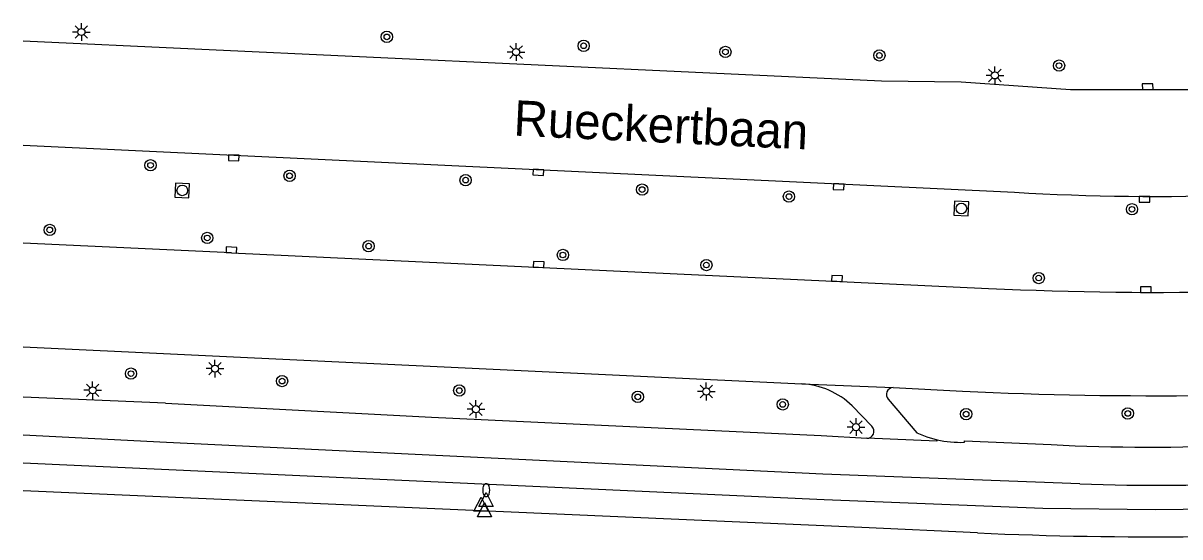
# Model space of a CAD drawing. Extents: x 132573 to 132944, y 398226 to 398676.
# Drawn here: x 132573 to 132654.8, y 398531 to 398567.3 of the extents above; entities that cross this region are included whole.
import ezdxf

# ---------------------------------------------------------------- set-up
doc = ezdxf.new("R2010")
doc.units = 0
for name, color, linetype in [('gg-anno-openbare ruimte label', 7, 'Continuous'), ('gg-knt-verharding', 7, 'Continuous'), ('gt-symb-boom', 7, 'Continuous'), ('gt-symb-brandkraan', 7, 'Continuous'), ('gt-symb-kolk', 7, 'Continuous'), ('gt-symb-lichtmast', 7, 'Continuous'), ('gt-symb-rioolschacht', 7, 'Continuous'), ('gt-symb-waterafsluiter', 7, 'Continuous')]:
    doc.layers.add(name, color=color, linetype=linetype)

msp = doc.modelspace()

# ---------------------------------------------------------------- linework, layer by layer
at = {"layer": 'gg-knt-verharding'}
for p, q in [((132573.021, 398558.665), (132587.916, 398557.963)), ((132587.916, 398557.963), (132643.07, 398555.33)), ((132587.734, 398551.055), (132573.021, 398551.736)), ((132587.734, 398551.055), (132641.243, 398548.55)), ((132573.021, 398544.411), (132628.051, 398541.809)), ((132628.051, 398541.809), (132634.494, 398541.539)), ((132583.077, 398540.449), (132573.021, 398540.872)), ((132634.494, 398541.539), (132639.4, 398541.29)), ((132632.997, 398538.808), (132631.596, 398540.256)), ((132639.54, 398537.68), (132639.553, 398537.781)), ((132639.553, 398537.781), (132645.663, 398537.514)), ((132629.629, 398533.623), (132573.021, 398536.217))]:
    msp.add_line(p, q, dxfattribs=at)
for points in [[(132573.021, 398566.028), (132633.671, 398563.201), (132639.312, 398563.126), (132647.044, 398562.601), (132652.489, 398562.588)], [(132583.077, 398540.449), (132601.878, 398539.466), (132629.419, 398538.153), (132632.633, 398537.963)], [(132634.149, 398540.722), (132636.163, 398538.34), (132636.87, 398538.066), (132637.6, 398537.863)], [(132647.686, 398534.74), (132629.537, 398535.429), (132583.159, 398537.66), (132573.021, 398538.184)], [(132637.6, 398537.863), (132637.582, 398537.756), (132632.633, 398537.963)], [(132640.467, 398531.279), (132632.29, 398531.665), (132573.021, 398534.264)], [(132678.938, 398533.726), (132660.959, 398533.003), (132653.017, 398532.913), (132645.08, 398533.003), (132629.629, 398533.623)]]:
    msp.add_lwpolyline(points, dxfattribs=at)
for centre, radius, start, end in [((132653.166, 398802.793), 240.206, 269.83859, 273.81384), ((132652.991, 398725.107), 170.066, 266.65564, 277.53525), ((132653.172, 398797.222), 248.958, 267.25349, 275.54025), ((132627.755, 398536.311), 5.506, 45.76621, 86.91909), ((132653.108, 398834.104), 293.135, 267.31972, 274.07391), ((132634.508, 398541.052), 0.487, 91.61115, 222.60246), ((132632.652, 398538.456), 0.493, 267.81374, 45.57648), ((132639.288, 398545.388), 7.712, 257.35342, 271.86906), ((132652.589, 398674.401), 137.062, 267.10354, 272.76093), ((132653.037, 398682.544), 147.9, 267.92677, 273.08843), ((132653.056, 398819.67), 288.666, 267.50056, 270.57669)]:
    msp.add_arc(centre, radius, start, end, dxfattribs=at)
at = {"layer": 'gt-symb-boom'}
for centre, radius in [((132598.723, 398566.307), 0.4), ((132598.723, 398566.307), 0.2), ((132612.631, 398565.676), 0.4), ((132612.631, 398565.676), 0.2), ((132622.65, 398565.24), 0.4), ((132622.65, 398565.24), 0.2), ((132633.527, 398564.995), 0.4), ((132633.527, 398564.995), 0.2), ((132646.222, 398564.276), 0.4), ((132646.222, 398564.276), 0.2), ((132582.022, 398557.238), 0.4), ((132582.022, 398557.238), 0.2), ((132591.848, 398556.496), 0.4), ((132591.848, 398556.496), 0.2), ((132604.292, 398556.19), 0.4), ((132604.292, 398556.19), 0.2), ((132616.764, 398555.525), 0.4), ((132616.764, 398555.525), 0.2), ((132627.138, 398555.03), 0.4), ((132627.138, 398555.03), 0.2), ((132651.379, 398554.13), 0.4), ((132651.379, 398554.13), 0.2), ((132574.9, 398552.676), 0.4), ((132574.9, 398552.676), 0.2), ((132586.032, 398552.109), 0.4), ((132586.032, 398552.109), 0.2), ((132597.435, 398551.53), 0.4), ((132597.435, 398551.53), 0.2), ((132611.163, 398550.905), 0.4), ((132611.163, 398550.905), 0.2), ((132621.302, 398550.196), 0.4), ((132621.302, 398550.196), 0.2), ((132644.787, 398549.28), 0.4), ((132644.787, 398549.28), 0.2), ((132580.643, 398542.528), 0.4), ((132580.643, 398542.528), 0.2), ((132591.321, 398542.003), 0.4), ((132591.321, 398542.003), 0.2), ((132603.842, 398541.335), 0.4), ((132603.842, 398541.335), 0.2), ((132616.457, 398540.888), 0.4), ((132616.457, 398540.888), 0.2), ((132626.695, 398540.354), 0.4), ((132626.695, 398540.354), 0.2), ((132639.658, 398539.67), 0.4), ((132651.082, 398539.717), 0.4), ((132639.658, 398539.67), 0.2), ((132651.082, 398539.717), 0.2)]:
    msp.add_circle(centre, radius, dxfattribs=at)
at = {"layer": 'gt-symb-brandkraan'}
for centre, radius, start, end in [((132606.436, 398534.302), 0.938, 163.10799, 196.89205), ((132608.409, 398533.703), 3, 162.43309, 163.10799), ((132605.745, 398534.546), 0.206, 17.56695, 162.43309), ((132603.081, 398533.703), 3, 16.89206, 17.56695), ((132605.054, 398534.302), 0.938, 343.10797, 16.89206), ((132608.409, 398534.901), 3, 196.89205, 197.56694), ((132605.745, 398534.058), 0.206, 197.56694, 342.43307), ((132603.081, 398534.901), 3, 342.43307, 343.10797)]:
    msp.add_arc(centre, radius, start, end, dxfattribs=at)
at = {"layer": 'gt-symb-kolk'}
for points in [[(132652.489, 398562.588), (132652.864, 398562.594), (132652.857, 398562.994), (132652.108, 398562.982), (132652.114, 398562.582), (132652.489, 398562.588)], [(132587.916, 398557.963), (132587.541, 398557.98), (132587.523, 398557.581), (132588.272, 398557.546), (132588.291, 398557.946), (132587.916, 398557.963)], [(132609.44, 398556.936), (132609.065, 398556.953), (132609.047, 398556.554), (132609.796, 398556.519), (132609.815, 398556.919), (132609.44, 398556.936)], [(132630.66, 398555.923), (132630.285, 398555.94), (132630.267, 398555.541), (132631.016, 398555.506), (132631.035, 398555.906), (132630.66, 398555.923)], [(132652.255, 398555.04), (132651.88, 398555.042), (132651.878, 398554.642), (132652.628, 398554.638), (132652.63, 398555.038), (132652.255, 398555.04)], [(132587.734, 398551.055), (132588.109, 398551.038), (132588.127, 398551.438), (132587.377, 398551.471), (132587.359, 398551.072), (132587.734, 398551.055)], [(132609.435, 398550.038), (132609.81, 398550.02), (132609.829, 398550.42), (132609.08, 398550.456), (132609.06, 398550.056), (132609.435, 398550.038)], [(132630.525, 398549.051), (132630.9, 398549.034), (132630.917, 398549.434), (132630.168, 398549.467), (132630.15, 398549.068), (132630.525, 398549.051)], [(132652.348, 398548.264), (132652.723, 398548.262), (132652.725, 398548.662), (132651.975, 398548.666), (132651.973, 398548.266), (132652.348, 398548.264)]]:
    msp.add_lwpolyline(points, dxfattribs=at)
at = {"layer": 'gt-symb-lichtmast'}
for p, q in [((132576.962, 398566.827), (132576.697, 398567.092)), ((132577.139, 398566.9), (132577.139, 398567.275)), ((132577.316, 398566.827), (132577.581, 398567.092)), ((132576.889, 398566.65), (132576.514, 398566.65)), ((132576.962, 398566.473), (132576.697, 398566.208)), ((132577.139, 398566.4), (132577.139, 398566.025)), ((132577.581, 398566.208), (132577.316, 398566.473)), ((132577.389, 398566.65), (132577.764, 398566.65)), ((132607.68, 398565.408), (132607.415, 398565.673)), ((132607.857, 398565.481), (132607.857, 398565.856)), ((132608.034, 398565.408), (132608.299, 398565.673)), ((132607.607, 398565.231), (132607.232, 398565.231)), ((132607.68, 398565.054), (132607.415, 398564.789)), ((132607.857, 398564.981), (132607.857, 398564.606)), ((132608.299, 398564.789), (132608.034, 398565.054)), ((132608.107, 398565.231), (132608.482, 398565.231)), ((132641.51, 398563.762), (132641.245, 398564.027)), ((132641.687, 398563.835), (132641.687, 398564.21)), ((132641.864, 398563.762), (132642.129, 398564.027)), ((132641.437, 398563.585), (132641.062, 398563.585)), ((132641.51, 398563.408), (132641.245, 398563.143)), ((132641.687, 398563.335), (132641.687, 398562.96)), ((132642.129, 398563.143), (132641.864, 398563.408)), ((132641.937, 398563.585), (132642.312, 398563.585)), ((132586.401, 398543.058), (132586.136, 398543.323)), ((132586.578, 398543.131), (132586.578, 398543.506)), ((132586.755, 398543.058), (132587.02, 398543.323)), ((132586.328, 398542.881), (132585.953, 398542.881)), ((132586.401, 398542.704), (132586.136, 398542.439)), ((132586.578, 398542.631), (132586.578, 398542.256)), ((132587.02, 398542.439), (132586.755, 398542.704)), ((132586.828, 398542.881), (132587.203, 398542.881)), ((132577.754, 398541.53), (132577.489, 398541.795)), ((132577.931, 398541.603), (132577.931, 398541.978)), ((132578.108, 398541.53), (132578.373, 398541.795)), ((132621.12, 398541.444), (132620.855, 398541.709)), ((132621.297, 398541.517), (132621.297, 398541.892)), ((132621.474, 398541.444), (132621.739, 398541.709)), ((132577.681, 398541.353), (132577.306, 398541.353)), ((132577.754, 398541.176), (132577.489, 398540.911)), ((132577.931, 398541.103), (132577.931, 398540.728)), ((132578.373, 398540.911), (132578.108, 398541.176)), ((132578.181, 398541.353), (132578.556, 398541.353)), ((132621.047, 398541.267), (132620.672, 398541.267)), ((132621.12, 398541.09), (132620.855, 398540.825)), ((132621.297, 398541.017), (132621.297, 398540.642)), ((132621.739, 398540.825), (132621.474, 398541.09)), ((132621.547, 398541.267), (132621.922, 398541.267)), ((132604.767, 398540.019), (132604.392, 398540.019)), ((132604.84, 398540.196), (132604.575, 398540.461)), ((132605.017, 398540.269), (132605.017, 398540.644)), ((132605.194, 398540.196), (132605.459, 398540.461)), ((132605.267, 398540.019), (132605.642, 398540.019)), ((132604.84, 398539.842), (132604.575, 398539.577)), ((132605.017, 398539.769), (132605.017, 398539.394)), ((132605.459, 398539.577), (132605.194, 398539.842)), ((132631.699, 398538.928), (132631.434, 398539.193)), ((132631.876, 398539.001), (132631.876, 398539.376)), ((132632.053, 398538.928), (132632.318, 398539.193)), ((132631.626, 398538.751), (132631.251, 398538.751)), ((132631.699, 398538.574), (132631.434, 398538.309)), ((132631.876, 398538.501), (132631.876, 398538.126)), ((132632.318, 398538.309), (132632.053, 398538.574)), ((132632.126, 398538.751), (132632.501, 398538.751))]:
    msp.add_line(p, q, dxfattribs=at)
for centre in [(132577.139, 398566.65), (132607.857, 398565.231), (132641.687, 398563.585), (132586.578, 398542.881), (132577.931, 398541.353), (132621.297, 398541.267), (132605.017, 398540.019), (132631.876, 398538.751)]:
    msp.add_circle(centre, 0.25, dxfattribs=at)
at = {"layer": 'gt-symb-rioolschacht'}
for points in [[(132584.74, 398554.942), (132584.788, 398555.94), (132583.79, 398555.988), (132583.742, 398554.99)], [(132639.797, 398553.661), (132639.845, 398554.659), (132638.847, 398554.707), (132638.799, 398553.709)]]:
    msp.add_lwpolyline(points, close=True, dxfattribs=at)
for centre in [(132584.265, 398555.465), (132639.322, 398554.184)]:
    msp.add_circle(centre, 0.375, dxfattribs=at)
at = {"layer": 'gt-symb-waterafsluiter'}
for p, q in [((132604.877, 398532.811), (132605.377, 398533.811)), ((132605.233, 398533.138), (132605.733, 398534.138)), ((132605.377, 398533.811), (132605.877, 398532.811)), ((132605.733, 398534.138), (132606.233, 398533.138)), ((132605.877, 398532.811), (132604.877, 398532.811)), ((132605.119, 398532.424), (132605.619, 398533.424)), ((132606.233, 398533.138), (132605.233, 398533.138)), ((132605.619, 398533.424), (132606.119, 398532.424)), ((132606.119, 398532.424), (132605.119, 398532.424))]:
    msp.add_line(p, q, dxfattribs=at)

# ---------------------------------------------------------------- texts
at = {"layer": 'gg-anno-openbare ruimte label'}
msp.add_text('Rueckertbaan', height=2.5, rotation=357.3, dxfattribs=at).set_placement((132607.645, 398559.339))

doc.saveas('drawing.dxf')
